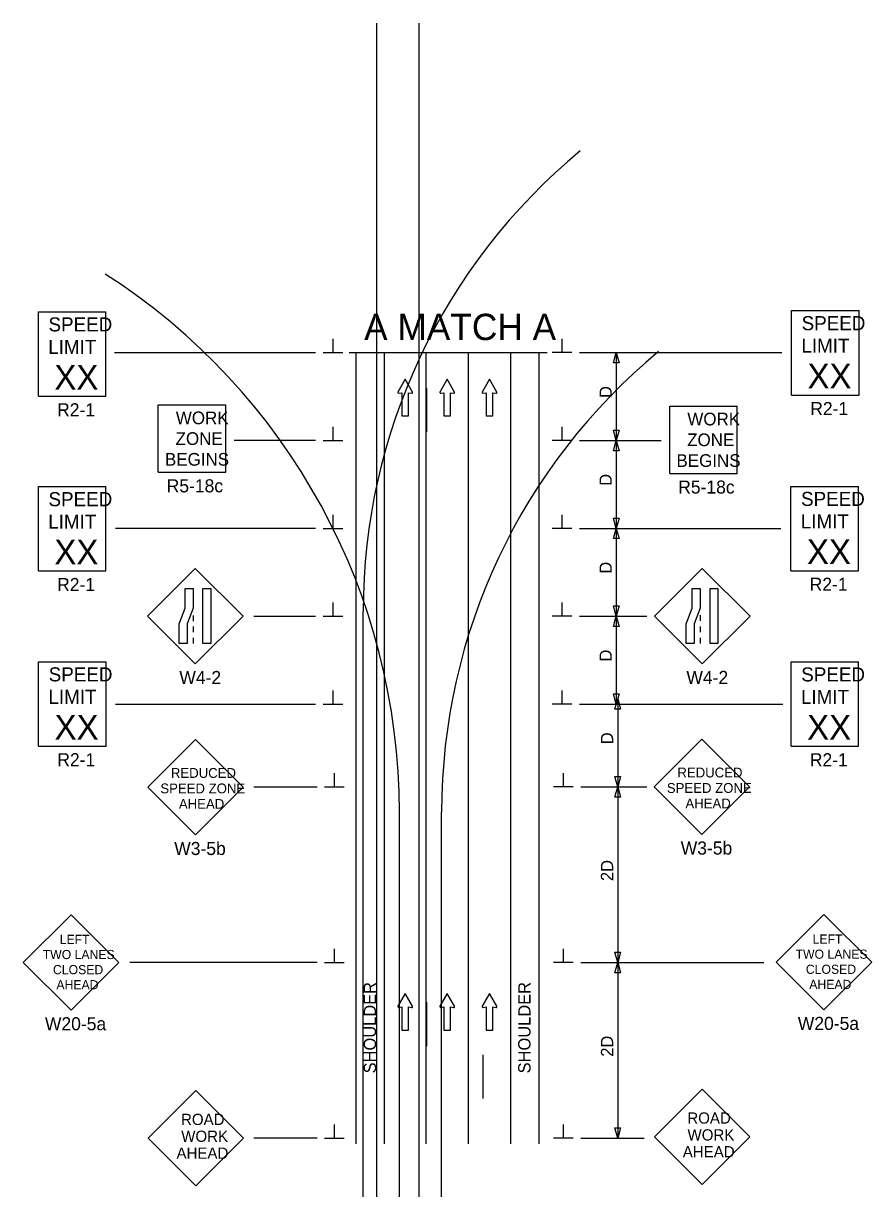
# Model space of a CAD drawing. Extents: x 16552 to 19508, y 5713 to 7079.
# Drawn here: x 17854 to 18336, y 6416 to 7079 of the extents above; entities that cross this region are included whole.
import ezdxf

# ---------------------------------------------------------------- set-up
doc = ezdxf.new("R2010")
doc.units = 0
for name, color, linetype in [('ALI_LEGAL_EX', 7, 'Continuous'), ('MT_SCRATCH_LEVEL_E', 7, 'Continuous'), ('PAVT_EDGE_EX', 7, 'Continuous'), ('TRAFFIC_SIGNS_PR', 7, 'Continuous'), ('TYPICAL_TEXT_DIMEN_PR', 7, 'Continuous')]:
    doc.layers.add(name, color=color, linetype=linetype)

msp = doc.modelspace()

# ---------------------------------------------------------------- linework, layer by layer
at = {"layer": 'ALI_LEGAL_EX'}
for p, q in [((18054.48, 7078.99), (18054.48, 6260.86)), ((18078.48, 7078.99), (18078.48, 6260.86)), ((18054.48, 6981.91), (18054.48, 6118)), ((18078.48, 6981.91), (18078.48, 6118)), ((18082.72, 6441.2), (18082.72, 6891.55)), ((18106.72, 6441.2), (18106.72, 6891.55)), ((18046.81, 6243.91), (18046.81, 6744.25)), ((18067.45, 6129.67), (18067.45, 6630.02)), ((18091.45, 6129.67), (18091.45, 6630.02))]:
    msp.add_line(p, q, dxfattribs=at)
for points in [[(18082.81, 6871.42), (18082.81, 6846.42)], [(18082.72, 6841.2), (18082.72, 6866.2)], [(18106.72, 6841.2), (18106.72, 6866.2)], [(18082.72, 6741.2), (18082.72, 6766.2)], [(18106.72, 6741.2), (18106.72, 6766.2)], [(18082.72, 6641.2), (18082.72, 6666.2)], [(18106.72, 6641.2), (18106.72, 6666.2)], [(18082.72, 6541.2), (18082.72, 6566.2)], [(18106.72, 6541.2), (18106.72, 6566.2)], [(18082.81, 6521.86), (18082.81, 6496.86)], [(18114.95, 6491.99), (18114.95, 6466.99)], [(18082.72, 6441.2), (18082.72, 6466.2)], [(18106.72, 6441.2), (18106.72, 6466.2)]]:
    msp.add_lwpolyline(points, dxfattribs=at)
for centre, radius, start, end in [((18386.81, 6744.25), 340, 129.56655, 180), ((17703.45, 6630.02), 364, 0, 57.29578), ((18431.45, 6630.02), 340, 129.56655, 180)]:
    msp.add_arc(centre, radius, start, end, dxfattribs=at)
at = {"layer": 'MT_SCRATCH_LEVEL_E'}
for p, q in [((18070.73, 6876.38), (18066.62, 6869.14)), ((18074.88, 6869.14), (18070.73, 6876.38)), ((18094.64, 6876.38), (18090.53, 6869.14)), ((18098.78, 6869.14), (18094.64, 6876.38)), ((18118.69, 6876.38), (18114.58, 6869.14)), ((18122.84, 6869.14), (18118.69, 6876.38)), ((18067.1, 6868.46), (18068.88, 6868.77)), ((18068.88, 6868.77), (18068.88, 6855.51)), ((18072.62, 6855.51), (18072.62, 6868.77)), ((18072.62, 6868.77), (18074.4, 6868.46)), ((18091.01, 6868.46), (18092.78, 6868.77)), ((18092.78, 6868.77), (18092.78, 6855.51)), ((18096.53, 6855.51), (18096.53, 6868.77)), ((18096.53, 6868.77), (18098.3, 6868.46)), ((18115.06, 6868.46), (18116.84, 6868.77)), ((18116.84, 6868.77), (18116.84, 6855.51)), ((18120.58, 6855.51), (18120.58, 6868.77)), ((18120.58, 6868.77), (18122.36, 6868.46)), ((18068.88, 6855.51), (18072.62, 6855.51)), ((18092.78, 6855.51), (18096.53, 6855.51)), ((18116.84, 6855.51), (18120.58, 6855.51)), ((18070.73, 6526.83), (18066.62, 6519.59)), ((18074.88, 6519.59), (18070.73, 6526.83)), ((18094.64, 6526.83), (18090.53, 6519.59)), ((18098.78, 6519.59), (18094.64, 6526.83)), ((18118.69, 6526.83), (18114.58, 6519.59)), ((18122.84, 6519.59), (18118.69, 6526.83)), ((18067.1, 6518.9), (18068.88, 6519.22)), ((18068.88, 6519.22), (18068.88, 6505.96)), ((18072.62, 6505.96), (18072.62, 6519.22)), ((18072.62, 6519.22), (18074.4, 6518.9)), ((18091.01, 6518.9), (18092.78, 6519.22)), ((18092.78, 6519.22), (18092.78, 6505.96)), ((18096.53, 6505.96), (18096.53, 6519.22)), ((18096.53, 6519.22), (18098.3, 6518.9)), ((18115.06, 6518.9), (18116.84, 6519.22)), ((18116.84, 6519.22), (18116.84, 6505.96)), ((18120.58, 6505.96), (18120.58, 6519.22)), ((18120.58, 6519.22), (18122.36, 6518.9)), ((18068.88, 6505.96), (18072.62, 6505.96)), ((18092.78, 6505.96), (18096.53, 6505.96)), ((18116.84, 6505.96), (18120.58, 6505.96))]:
    msp.add_line(p, q, dxfattribs=at)
for centre, start, end in [((18067.03, 6868.91), 150.42484, 279.96381), ((18074.47, 6868.91), 260.03619, 29.77312), ((18090.93, 6868.91), 150.42484, 279.96381), ((18098.37, 6868.91), 260.03619, 29.77312), ((18114.99, 6868.91), 150.42484, 279.96381), ((18122.43, 6868.91), 260.03619, 29.77312), ((18067.03, 6519.36), 150.42484, 279.96381), ((18074.47, 6519.36), 260.03619, 29.77312), ((18090.93, 6519.36), 150.42484, 279.96381), ((18098.37, 6519.36), 260.03619, 29.77312), ((18114.99, 6519.36), 150.42484, 279.96381), ((18122.43, 6519.36), 260.03619, 29.77312)]:
    msp.add_arc(centre, 0.463, start, end, dxfattribs=at)
at = {"layer": 'PAVT_EDGE_EX'}
for p, q in [((18042.72, 6891.55), (18042.72, 6441.2)), ((18058.72, 6891.55), (18058.72, 6441.2)), ((18130.72, 6891.55), (18130.72, 6441.2)), ((18146.72, 6891.55), (18146.72, 6441.2))]:
    msp.add_line(p, q, dxfattribs=at)
at = {"layer": 'TRAFFIC_SIGNS_PR'}
for p, q in [((17862.08, 6914.76), (17900.48, 6914.76)), ((17862.08, 6866.76), (17862.08, 6914.76)), ((17900.48, 6866.76), (17900.48, 6914.76)), ((18290.46, 6915.45), (18328.86, 6915.45)), ((18290.46, 6867.45), (18290.46, 6915.45)), ((18328.86, 6867.45), (18328.86, 6915.45)), ((17862.08, 6866.76), (17900.48, 6866.76)), ((18290.46, 6867.45), (18328.86, 6867.45)), ((17930.27, 6823.48), (17930.27, 6861.88)), ((17930.27, 6861.88), (17968.67, 6861.88)), ((17968.67, 6823.48), (17968.67, 6861.88)), ((18221.21, 6822.79), (18221.21, 6861.19)), ((18221.21, 6861.19), (18259.61, 6861.19)), ((18259.61, 6822.79), (18259.61, 6861.19)), ((17930.27, 6823.48), (17968.67, 6823.48)), ((18221.21, 6822.79), (18259.61, 6822.79)), ((17862.08, 6815.31), (17900.48, 6815.31)), ((17862.08, 6767.31), (17862.08, 6815.31)), ((17900.48, 6767.31), (17900.48, 6815.31)), ((18290.12, 6815.46), (18328.52, 6815.46)), ((18290.12, 6767.46), (18290.12, 6815.46)), ((18328.52, 6767.46), (18328.52, 6815.46)), ((17862.08, 6767.31), (17900.48, 6767.31)), ((17951.32, 6768.69), (17924.17, 6741.54)), ((17978.48, 6741.54), (17951.32, 6768.69)), ((18239.72, 6768.75), (18212.57, 6741.6)), ((18266.87, 6741.6), (18239.72, 6768.75)), ((18290.12, 6767.46), (18328.52, 6767.46)), ((17924.17, 6741.54), (17951.32, 6714.39)), ((17950.08, 6742.03), (17950.08, 6738.83)), ((17951.32, 6714.39), (17978.48, 6741.54)), ((18212.57, 6741.6), (18239.72, 6714.44)), ((18238.47, 6742.09), (18238.47, 6738.89)), ((18239.72, 6714.44), (18266.87, 6741.6)), ((17950.08, 6735.63), (17950.08, 6732.43)), ((18238.47, 6735.69), (18238.47, 6732.49)), ((17950.08, 6729.23), (17950.08, 6726.03)), ((18238.47, 6729.29), (18238.47, 6726.09)), ((17862.19, 6715.6), (17900.59, 6715.6)), ((17862.19, 6667.6), (17862.19, 6715.6)), ((17900.59, 6667.6), (17900.59, 6715.6)), ((18290.23, 6715.57), (18328.63, 6715.57)), ((18290.23, 6667.57), (18290.23, 6715.57)), ((18328.63, 6667.57), (18328.63, 6715.57)), ((17862.19, 6667.6), (17900.59, 6667.6)), ((17951.41, 6671.38), (17924.26, 6644.23)), ((17978.57, 6644.23), (17951.41, 6671.38)), ((18239.51, 6671.64), (18212.35, 6644.49)), ((18266.66, 6644.49), (18239.51, 6671.64)), ((18290.23, 6667.57), (18328.63, 6667.57)), ((17924.26, 6644.23), (17951.41, 6617.08)), ((17951.41, 6617.08), (17978.57, 6644.23)), ((18212.35, 6644.49), (18239.51, 6617.34)), ((18239.51, 6617.34), (18266.66, 6644.49)), ((17880.68, 6571.64), (17853.53, 6544.48)), ((17907.84, 6544.48), (17880.68, 6571.64)), ((18308.91, 6571.83), (18281.76, 6544.68)), ((18336.06, 6544.68), (18308.91, 6571.83)), ((17853.53, 6544.48), (17880.68, 6517.33)), ((17880.68, 6517.33), (17907.84, 6544.48)), ((18281.76, 6544.68), (18308.91, 6517.52)), ((18308.91, 6517.52), (18336.06, 6544.68)), ((17951.7, 6471.6), (17924.55, 6444.45)), ((17978.85, 6444.45), (17951.7, 6471.6)), ((18239.67, 6472.38), (18212.52, 6445.23)), ((18266.82, 6445.23), (18239.67, 6472.38)), ((17924.55, 6444.45), (17951.7, 6417.3)), ((17951.7, 6417.3), (17978.85, 6444.45)), ((18212.52, 6445.23), (18239.67, 6418.07)), ((18239.67, 6418.07), (18266.82, 6445.23))]:
    msp.add_line(p, q, dxfattribs=at)
for points in [[(17950.08, 6757.28), (17950.08, 6746.09), (17946.73, 6737.21), (17946.73, 6726.03), (17942.24, 6726.03), (17942.24, 6737.21), (17945.58, 6746.09), (17945.58, 6757.28)], [(17960.21, 6757.28), (17960.21, 6726.03), (17955.72, 6726.03), (17955.72, 6757.28)], [(18238.47, 6757.33), (18238.47, 6746.15), (18235.13, 6737.27), (18235.13, 6726.09), (18230.64, 6726.09), (18230.64, 6737.27), (18233.98, 6746.15), (18233.98, 6757.33)], [(18248.61, 6757.33), (18248.61, 6726.09), (18244.12, 6726.09), (18244.12, 6757.33)]]:
    msp.add_lwpolyline(points, close=True, dxfattribs=at)
at = {"layer": 'TYPICAL_TEXT_DIMEN_PR'}
for p, q in [((18029.69, 6891.55), (18029.69, 6899.34)), ((18159.94, 6891.55), (18159.94, 6899.34)), ((17905.34, 6891.55), (18019.81, 6891.55)), ((18024.06, 6891.55), (18035.31, 6891.55)), ((18038.79, 6891.55), (18151.44, 6891.55)), ((18165.56, 6891.55), (18154.31, 6891.55)), ((18169.81, 6891.55), (18284.96, 6891.55)), ((18189.24, 6885.69), (18190.81, 6891.55)), ((18190.81, 6891.55), (18190.81, 6841.55)), ((18190.81, 6891.55), (18192.39, 6885.69)), ((18190.81, 6885.69), (18189.24, 6885.69)), ((18192.39, 6885.69), (18190.81, 6885.69)), ((18029.69, 6841.55), (18029.69, 6849.34)), ((18159.94, 6841.55), (18159.94, 6849.34)), ((18190.81, 6841.55), (18189.24, 6847.41)), ((18189.24, 6847.41), (18190.81, 6847.41)), ((18190.81, 6847.41), (18192.39, 6847.41)), ((18192.39, 6847.41), (18190.81, 6841.55)), ((18019.81, 6841.55), (17973.46, 6841.55)), ((18024.06, 6841.55), (18035.31, 6841.55)), ((18165.56, 6841.55), (18154.31, 6841.55)), ((18169.81, 6841.55), (18216.29, 6841.55)), ((18189.24, 6835.69), (18190.81, 6841.55)), ((18190.81, 6841.55), (18192.39, 6835.69)), ((18190.81, 6841.55), (18190.81, 6791.55)), ((18190.81, 6835.69), (18189.24, 6835.69)), ((18192.39, 6835.69), (18190.81, 6835.69)), ((18029.69, 6791.55), (18029.69, 6799.34)), ((18159.94, 6791.55), (18159.94, 6799.34)), ((18190.81, 6791.55), (18189.24, 6797.41)), ((18189.24, 6797.41), (18190.81, 6797.41)), ((18190.81, 6797.41), (18192.39, 6797.41)), ((18192.39, 6797.41), (18190.81, 6791.55)), ((18019.81, 6791.55), (17905.89, 6791.55)), ((18024.06, 6791.55), (18035.31, 6791.55)), ((18165.56, 6791.55), (18154.31, 6791.55)), ((18169.81, 6791.55), (18284.41, 6791.55)), ((18189.24, 6785.69), (18190.81, 6791.55)), ((18190.81, 6785.69), (18189.24, 6785.69)), ((18190.81, 6791.55), (18190.81, 6741.55)), ((18190.81, 6791.55), (18192.39, 6785.69)), ((18192.39, 6785.69), (18190.81, 6785.69)), ((18029.69, 6741.55), (18029.69, 6749.34)), ((18159.94, 6741.55), (18159.94, 6749.34)), ((18190.81, 6741.55), (18189.24, 6747.41)), ((18189.24, 6747.41), (18190.81, 6747.41)), ((18190.81, 6747.41), (18192.39, 6747.41)), ((18192.39, 6747.41), (18190.81, 6741.55)), ((17984.6, 6741.55), (18019.81, 6741.55)), ((18024.06, 6741.55), (18035.31, 6741.55)), ((18165.56, 6741.55), (18154.31, 6741.55)), ((18169.81, 6741.55), (18208.16, 6741.55)), ((18189.24, 6735.69), (18190.81, 6741.55)), ((18190.81, 6741.55), (18190.81, 6691.55)), ((18190.81, 6741.55), (18192.39, 6735.69)), ((18190.81, 6735.69), (18189.24, 6735.69)), ((18192.39, 6735.69), (18190.81, 6735.69)), ((18029.69, 6691.55), (18029.69, 6699.34)), ((18159.94, 6691.55), (18159.94, 6699.34)), ((18190.81, 6691.55), (18189.24, 6697.41)), ((18189.24, 6697.41), (18190.81, 6697.41)), ((18190.03, 6688.62), (18191.6, 6694.48)), ((18190.81, 6697.41), (18192.39, 6697.41)), ((18192.39, 6697.41), (18190.81, 6691.55)), ((18191.6, 6694.48), (18191.6, 6644.48)), ((18191.6, 6694.48), (18193.17, 6688.62)), ((17905.89, 6691.55), (18019.81, 6691.55)), ((18024.06, 6691.55), (18035.31, 6691.55)), ((18165.56, 6691.55), (18154.31, 6691.55)), ((18169.81, 6691.55), (18285.51, 6691.55)), ((18191.6, 6688.62), (18190.03, 6688.62)), ((18193.17, 6688.62), (18191.6, 6688.62)), ((18030.48, 6644.48), (18030.48, 6652.27)), ((18160.73, 6644.48), (18160.73, 6652.27)), ((18191.6, 6644.48), (18190.03, 6650.34)), ((18190.03, 6650.34), (18191.6, 6650.34)), ((18191.6, 6650.34), (18193.17, 6650.34)), ((18193.17, 6650.34), (18191.6, 6644.48)), ((17984.6, 6644.48), (18020.6, 6644.48)), ((18024.85, 6644.48), (18036.1, 6644.48)), ((18166.35, 6644.48), (18155.1, 6644.48)), ((18170.6, 6644.48), (18208.16, 6644.48)), ((18190.03, 6638.62), (18191.6, 6644.48)), ((18191.6, 6644.48), (18191.6, 6544.48)), ((18191.6, 6644.48), (18193.17, 6638.62)), ((18191.6, 6638.62), (18190.03, 6638.62)), ((18193.17, 6638.62), (18191.6, 6638.62)), ((18030.48, 6544.48), (18030.48, 6552.27)), ((18160.73, 6544.48), (18160.73, 6552.27)), ((18191.6, 6544.48), (18190.03, 6550.34)), ((18190.03, 6550.34), (18191.6, 6550.34)), ((18191.6, 6550.34), (18193.17, 6550.34)), ((18193.17, 6550.34), (18191.6, 6544.48)), ((18020.6, 6544.48), (17914.02, 6544.48)), ((18024.85, 6544.48), (18036.1, 6544.48)), ((18166.35, 6544.48), (18155.1, 6544.48)), ((18170.6, 6544.48), (18274.63, 6544.48)), ((18190.03, 6538.62), (18191.6, 6544.48)), ((18191.6, 6544.48), (18191.6, 6444.48)), ((18191.6, 6544.48), (18193.17, 6538.62)), ((18191.6, 6538.62), (18190.03, 6538.62)), ((18193.17, 6538.62), (18191.6, 6538.62)), ((18030.48, 6444.48), (18030.48, 6452.27)), ((18160.73, 6444.48), (18160.73, 6452.27)), ((18191.6, 6444.48), (18190.03, 6450.34)), ((18190.03, 6450.34), (18191.6, 6450.34)), ((18191.6, 6450.34), (18193.17, 6450.34)), ((18193.17, 6450.34), (18191.6, 6444.48)), ((18020.6, 6444.48), (17984.6, 6444.48)), ((18024.85, 6444.48), (18036.1, 6444.48)), ((18166.35, 6444.48), (18155.1, 6444.48)), ((18170.6, 6444.48), (18206.6, 6444.48))]:
    msp.add_line(p, q, dxfattribs=at)

# ---------------------------------------------------------------- texts
at = {"layer": 'TRAFFIC_SIGNS_PR'}
for s, height, p in [('SPEED', 8, (17867.85, 6903.63)), ('SPEED', 8, (18296.23, 6904.32)), ('LIMIT', 8, (17867.69, 6890.83)), ('LIMIT', 8, (18296.07, 6891.52)), ('XX', 14.031, (18299.57, 6871.21)), ('XX', 14.031, (17871.19, 6870.52)), ('R2-1', 7.44, (17872.76, 6855.32)), ('WORK', 7.217, (17940.27, 6850.84)), ('R2-1', 7.44, (18301.14, 6856.01)), ('WORK', 7.217, (18231.21, 6850.15)), ('ZONE', 7.217, (17940.15, 6839.03)), ('ZONE', 7.217, (18231.1, 6838.34)), ('BEGINS', 7.217, (17934.08, 6827.23)), ('BEGINS', 7.217, (18225.02, 6826.54)), ('R5-18c', 7.44, (17935.08, 6812.04)), ('R5-18c', 7.44, (18226.03, 6811.35)), ('SPEED', 8, (17867.85, 6804.17)), ('SPEED', 8, (18295.88, 6804.32)), ('LIMIT', 8, (17867.69, 6791.37)), ('LIMIT', 8, (18295.72, 6791.52)), ('XX', 14.031, (17871.19, 6771.07)), ('XX', 14.031, (18299.23, 6771.22)), ('R2-1', 7.44, (17872.76, 6755.87)), ('R2-1', 7.44, (18300.79, 6756.02)), ('SPEED', 8, (17867.96, 6704.46)), ('SPEED', 8, (18296, 6704.43)), ('W4-2', 7.44, (17942.28, 6702.95)), ('W4-2', 7.44, (18230.68, 6703)), ('LIMIT', 8, (17867.8, 6691.66)), ('LIMIT', 8, (18295.84, 6691.63)), ('XX', 14.031, (17871.3, 6671.36)), ('XX', 14.031, (18299.34, 6671.32)), ('R2-1', 7.44, (17872.87, 6656.16)), ('R2-1', 7.44, (18300.91, 6656.13)), ('REDUCED', 5.6, (17937.47, 6649.54)), ('REDUCED', 5.6, (18225.56, 6649.8)), ('SPEED ZONE', 5.6, (17931.46, 6640.74)), ('SPEED ZONE', 5.6, (18219.56, 6641)), ('AHEAD', 5.6, (17942.02, 6631.94)), ('AHEAD', 5.6, (18230.12, 6632.2)), ('W3-5b', 7.44, (17939.37, 6605.64)), ('W3-5b', 7.44, (18227.46, 6605.9)), ('LEFT', 5.2, (17874.22, 6555.02)), ('LEFT', 5.2, (18302.45, 6555.21)), ('TWO LANES', 5.2, (17864.54, 6546.42)), ('TWO LANES', 5.2, (18292.77, 6546.61)), ('CLOSED', 5.2, (17870.39, 6537.82)), ('CLOSED', 5.2, (18298.62, 6538.01)), ('AHEAD', 5.2, (17872.34, 6529.22)), ('AHEAD', 5.2, (18300.57, 6529.41)), ('W20-5a', 7.44, (17865.82, 6505.89)), ('W20-5a', 7.44, (18294.05, 6506.09)), ('ROAD', 6.4, (17943.24, 6451.98)), ('ROAD', 6.4, (18231.21, 6452.76)), ('WORK', 6.4, (17943.35, 6442.38)), ('WORK', 6.4, (18231.32, 6443.16)), ('AHEAD', 6.4, (17940.66, 6432.78)), ('AHEAD', 6.4, (18228.63, 6433.56))]:
    msp.add_text(s, height=height, dxfattribs=at).set_placement(p)
at = {"layer": 'TYPICAL_TEXT_DIMEN_PR'}
msp.add_text('A MATCH A', height=15, dxfattribs=at).set_placement((18047.38, 6898.69))
for s, p in [('D', (18188.26, 6865.77)), ('D', (18188.26, 6815.77)), ('D', (18188.26, 6765.77)), ('D', (18188.26, 6715.77)), ('D', (18189.04, 6668.7)), ('2D', (18189.04, 6590.85)), ('SHOULDER', (18054.15, 6481.37)), ('SHOULDER', (18142.01, 6481.37)), ('2D', (18189.04, 6490.85))]:
    msp.add_text(s, height=7, rotation=90, dxfattribs=at).set_placement(p)

doc.saveas('drawing.dxf')
